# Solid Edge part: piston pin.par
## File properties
Author: Vicky Raina
Template: Normal.par
Last saved by: Robert a Rhodes jr
Revision: 2
Application: Solid Edge
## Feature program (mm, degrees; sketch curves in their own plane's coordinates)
sketch for "unnamed Protrusion 1" #1 plane through (0, 0, 0) normal (0, 0, 1) x-axis (1, 0, 0)
  circle centre (0, 0) radius 5.5
sketch for "unnamed Protrusion 1" #2 plane through (0, 0, 0) normal (0, 0, 1) x-axis (1, 0, 0)
  circle centre (0, 0) radius 11
extrude "unnamed Protrusion 1" add finite 80 along -normal
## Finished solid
Body 1: solid body, 4 faces, 4 edges, 0 vertices.
  Faces by surface: cylinder 2, plane 2
  Edges by curve: circle 4
Bounding box of the edges (mm): 22.000 x 22.000 x 80.000, from (-11, -11, -80) to (11, 11, 0).
Cylindrical faces by radius (mm): R5.5 x1, R11 x1
Planar faces by outward normal: +z 1, -z 1
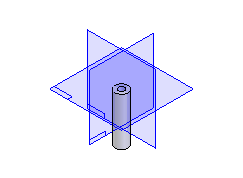
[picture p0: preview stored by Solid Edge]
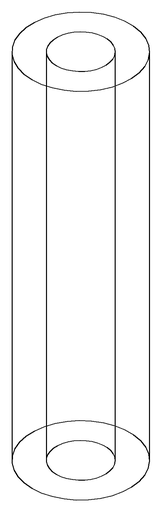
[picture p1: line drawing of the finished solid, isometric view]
